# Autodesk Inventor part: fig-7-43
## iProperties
Shininess: 77.0
Length Units: 11269
Angle Units: 11279
Time Units: 11290
Mass Units: 11283
Length Display Precision: 3
Angle Display Precision: 2
Created: 2002-01
Part Number: fig-7-43
Document SubType Name: Modeling
Designer: ***
Density: 1 g/cm^3
Density: 0.0
Volumn: 0.0
Area: 0.0
PropertySet Name: Model Information
Control State: 0
Master: False
Checked Out: False
Author: ***
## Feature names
1. Extrusion1
2. Shell2
